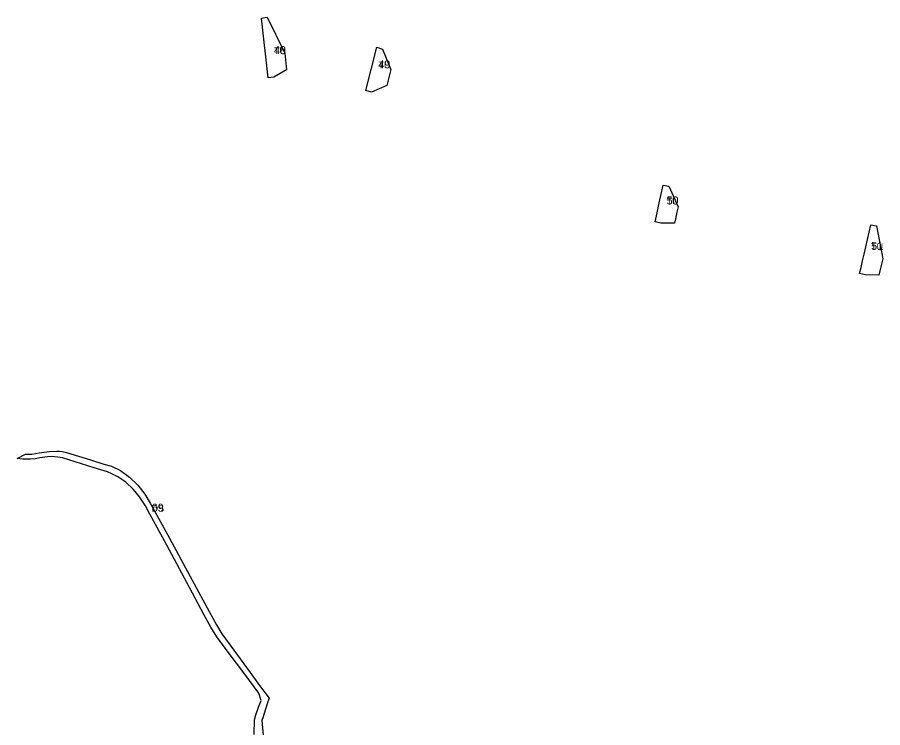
# Model space of a CAD drawing. Extents: x -535435 to -532834, y -1165802 to -1163866.
# Drawn here: x -534829 to -534180, y -1164698 to -1164165 of the extents above; entities that cross this region are included whole.
import ezdxf

# ---------------------------------------------------------------- set-up
doc = ezdxf.new("R2010")
doc.units = 0
for name, color, linetype in [('90320023', 7, 'Continuous'), ('90380023', 7, 'Continuous'), ('ID_navrh', 7, 'Continuous')]:
    doc.layers.add(name, color=color, linetype=linetype)

msp = doc.modelspace()

# ---------------------------------------------------------------- linework, layer by layer
at = {"layer": '90320023'}
msp.add_lwpolyline([(-534651.253, -1164703.409), (-534650.975, -1164692.251), (-534649.925, -1164688.576), (-534647.904, -1164682.84), (-534645.847, -1164677.959), (-534647.629, -1164672.429), (-534658.272, -1164658.05), (-534670.74, -1164641.717), (-534679.184, -1164630.139), (-534683.792, -1164622.823), (-534688.974, -1164613.292), (-534701.714, -1164589.354), (-534718.517, -1164558.022), (-534729.336, -1164538.044), (-534732.786, -1164531.828), (-534737.079, -1164525.158), (-534741.751, -1164519.514), (-534747.523, -1164514.089), (-534753.525, -1164510.08), (-534758.012, -1164507.727), (-534761.232, -1164506.36), (-534771.151, -1164503.333), (-534794.97, -1164495.874), (-534798.38, -1164495.209), (-534803.324, -1164494.852), (-534806.114, -1164495), (-534811.888, -1164495.833), (-534815.119, -1164496.425), (-534818.995, -1164496.791), (-534821.801, -1164496.902), (-534824.624, -1164496.838), (-534828.796, -1164496.418), (-534822.728, -1164493.033), (-534820.49, -1164493.143), (-534817.869, -1164493.052), (-534812.44, -1164492.038), (-534804.682, -1164491.006), (-534799.185, -1164490.795), (-534797.225, -1164490.889), (-534795.044, -1164491.154), (-534791.926, -1164491.894), (-534774.034, -1164497.362), (-534763.833, -1164500.668), (-534758.097, -1164502.081), (-534751.317, -1164505.211), (-534744.631, -1164510.374), (-534738.476, -1164516.319), (-534733.095, -1164523.114), (-534729.113, -1164529.776), (-534725.763, -1164536.1), (-534714.726, -1164556.06), (-534697.594, -1164587.582), (-534684.956, -1164611.107), (-534679.387, -1164621.172), (-534675.376, -1164627.896), (-534663.7, -1164643.954), (-534654.209, -1164656.789), (-534647.086, -1164666.492), (-534639.907, -1164676.108), (-534641.283, -1164679.593), (-534644.017, -1164688.264), (-534644.558, -1164690.047), (-534645.38, -1164692.752), (-534644.26, -1164706.72)], dxfattribs=at)
at = {"layer": '90380023'}
for points in [[(-534641.46, -1164165.28), (-534628.3, -1164192.26), (-534626.89, -1164204.68), (-534636.34, -1164210.08), (-534640.71, -1164210.58), (-534645.78, -1164165.89)], [(-534559.25, -1164187.61), (-534555.08, -1164189.08), (-534548.63, -1164204.4), (-534551.69, -1164216.52), (-534563.23, -1164221.34), (-534567.49, -1164220.26)], [(-534350.52, -1164318.78), (-534349.078, -1164312.05), (-534347.994, -1164306.993), (-534347.47, -1164304.55), (-534344.59, -1164291.11), (-534340.29, -1164292.04), (-534333.37, -1164307.48), (-534334.234, -1164311.511), (-534335.291, -1164316.439), (-534335.99, -1164319.7), (-534346.22, -1164319.71)], [(-534182.72, -1164358.73), (-534192.95, -1164358.6), (-534197.24, -1164357.62), (-534196.171, -1164352.932), (-534195.06, -1164348.062), (-534193.926, -1164343.087), (-534188.86, -1164320.87), (-534184.57, -1164321.84), (-534179.95, -1164346.54), (-534180.864, -1164350.562), (-534181.972, -1164355.438)]]:
    msp.add_lwpolyline(points, close=True, dxfattribs=at)

# ---------------------------------------------------------------- texts
at = {"layer": '90320023'}
msp.add_text('DS', height=5, rotation=0, dxfattribs=at).set_placement((-534728.003, -1164536.1884))
at = {"layer": '90380023'}
for rotation, p in [(360, (-534636.335, -1164192.9321)), (0, (-534558.06, -1164203.6051)), (0, (-534341.945, -1164305.6939)), (0, (-534188.595, -1164339.7926))]:
    msp.add_text('TU', height=5, rotation=rotation, dxfattribs=at).set_placement(p)
at = {"layer": 'ID_navrh'}
for s, rotation, p in [('48', 360, (-534636.335, -1164192.9321)), ('49', 0, (-534558.06, -1164203.6051)), ('50', 0, (-534341.945, -1164305.6939)), ('51', 360, (-534188.595, -1164339.7926)), ('69', 359.9999999, (-534728.003, -1164536.1884))]:
    msp.add_text(s, height=6, rotation=rotation, dxfattribs=at).set_placement(p)

doc.saveas('drawing.dxf')
